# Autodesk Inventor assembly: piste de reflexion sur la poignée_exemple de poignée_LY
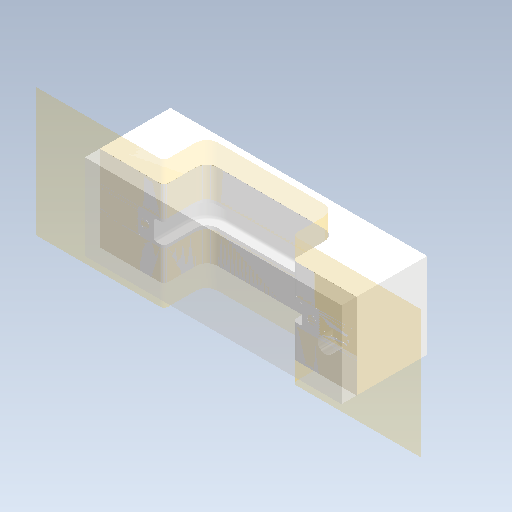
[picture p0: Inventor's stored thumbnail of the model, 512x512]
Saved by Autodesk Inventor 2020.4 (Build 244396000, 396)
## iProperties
Created: 2021-10
Part Number: piste de reflexion sur la poignée_exemple de poignée_LY
Document SubType Name: Assembly
Designer: mel
Author: mel
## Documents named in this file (2)
- D:\travail\année 2020-2021\itec\prépa injection plastique eduscol\dossier de travail\Ensemble des pièces de l'activité\Conception de moule2\piste de reflexion sur la poignée_exemple de poignée_LY.iam
- D:\travail\année 2020-2021\itec\prépa injection plastique eduscol\dossier de travail\Ensemble des pièces de l'activité\Conception de moule2\piste de reflexion sur la poignée_exemple de poignée_PZ.iam
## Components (1 placed, 1 different names)
1. piste de reflexion sur la poignée_exemple de poignée_PZ:1 [sub-assembly] — Affleurement:1, Affleurement:2, Affleurement:3
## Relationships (3: Flush 3)
- Affleurement:1 [Flush]: piste de reflexion sur la poignée_exemple de poignée_PZ:1
- Affleurement:2 [Flush]: piste de reflexion sur la poignée_exemple de poignée_PZ:1
- Affleurement:3 [Flush]: piste de reflexion sur la poignée_exemple de poignée_PZ:1
